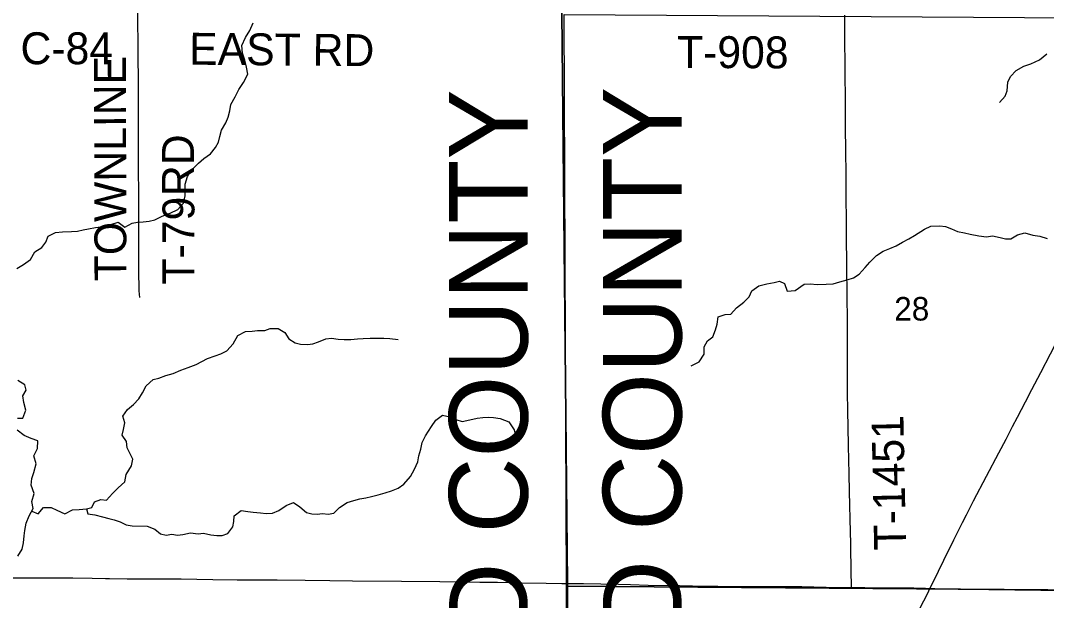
# Model space of a CAD drawing. Extents: x 0 to 70.2, y 0 to 31.4.
# Drawn here: x 5.776 to 7.601, y 19.29 to 20.322 of the extents above; entities that cross this region are included whole.
import ezdxf

# ---------------------------------------------------------------- set-up
doc = ezdxf.new("R2010")
doc.units = 0
for name, color, linetype in [('GM_X_County_Road', 7, 'Continuous'), ('GM_X_County_Road_Text', 7, 'Continuous'), ('GM_X_Minor_River', 7, 'Continuous'), ('GM_X_Section', 7, 'Continuous'), ('GM_X_Section_Text', 7, 'Continuous'), ('GM_X_State_Route', 7, 'Continuous'), ('GM_X_Township_Road', 7, 'Continuous'), ('GM_X_Township_Road_Text', 7, 'Continuous'), ('SH_Cut_Line', 7, 'Continuous'), ('SH_Text', 7, 'Continuous')]:
    doc.layers.add(name, color=color, linetype=linetype)

msp = doc.modelspace()

# ---------------------------------------------------------------- linework, layer by layer
at = {"layer": 'GM_X_County_Road'}
msp.add_lwpolyline([(7.3941, 19.311), (7.403, 19.311), (7.4442, 19.31), (7.4991, 19.3095), (7.5914, 19.3084), (7.6909, 19.3076), (7.7157, 19.3075), (7.7468, 19.3072), (7.7779, 19.3068), (7.8121, 19.3068), (7.868, 19.3063), (7.8928, 19.3063), (7.9239, 19.3068), (7.9394, 19.3066), (7.9518, 19.3064), (8.014, 19.3062), (8.0793, 19.3059), (8.1383, 19.3056), (8.1632, 19.3054), (8.1911, 19.3053), (8.2253, 19.3053), (8.2408, 19.3052), (8.2663, 19.3051), (8.2677, 19.3051)], dxfattribs=at)
at = {"layer": 'GM_X_Minor_River'}
for points in [[(6.0558, 19.9858), (6.0661, 19.9971), (6.0692, 20.01), (6.0689, 20.0202), (6.0689, 20.0312), (6.0732, 20.0445), (6.0797, 20.0551), (6.0926, 20.0683), (6.1022, 20.0766), (6.114, 20.0849), (6.1231, 20.0959), (6.1285, 20.1057), (6.1308, 20.1156), (6.1335, 20.1269), (6.1412, 20.1402), (6.1454, 20.15), (6.1485, 20.1614), (6.1501, 20.1728), (6.1581, 20.1864), (6.1646, 20.1997), (6.173, 20.2121), (6.1807, 20.2265), (6.1785, 20.2391), (6.1751, 20.2516), (6.1714, 20.2641), (6.1699, 20.2778), (6.1764, 20.2918), (6.1841, 20.3047), (6.1899, 20.3179)], [(7.5177, 20.1763), (7.5276, 20.1873), (7.5314, 20.1971), (7.5329, 20.2127), (7.5371, 20.2225), (7.5473, 20.2335), (7.561, 20.2407), (7.5735, 20.2453), (7.5887, 20.2525), (7.602, 20.2631)], [(5.7696, 19.8809), (5.7814, 19.8877), (5.794, 19.8971), (5.8016, 19.9103), (5.8142, 19.9179), (5.821, 19.9277), (5.8257, 19.9383), (5.8382, 19.9447), (5.8511, 19.9458), (5.8667, 19.9464), (5.8777, 19.9475), (5.8879, 19.9494), (5.8974, 19.9516), (5.9096, 19.9538), (5.9236, 19.9557), (5.9369, 19.9594), (5.9499, 19.9635), (5.9619, 19.9543), (5.9749, 19.9615), (5.9844, 19.963), (5.9946, 19.964), (6.0053, 19.9651), (6.0151, 19.9674), (6.0284, 19.9737), (6.0425, 19.9794), (6.0558, 19.9858)], [(6.9695, 19.7073), (6.9835, 19.7149), (6.9926, 19.7281), (6.9926, 19.7414), (6.9983, 19.752), (7.0078, 19.7592), (7.0123, 19.7714), (7.0154, 19.7816), (7.0173, 19.7945), (7.0298, 19.7991), (7.0397, 19.7998), (7.0499, 19.8108), (7.0628, 19.821), (7.0723, 19.8301), (7.0772, 19.8411), (7.0897, 19.8502), (7.1038, 19.8533), (7.1167, 19.8559), (7.1262, 19.8582), (7.1356, 19.8544), (7.1402, 19.8404), (7.1542, 19.8419), (7.1705, 19.8529), (7.1808, 19.8536), (7.1933, 19.8525), (7.2092, 19.8528), (7.2217, 19.8536), (7.2335, 19.857), (7.2468, 19.8608), (7.2578, 19.8642), (7.268, 19.8706), (7.2786, 19.8824), (7.287, 19.8919), (7.2987, 19.904), (7.3109, 19.9116), (7.3226, 19.9165), (7.334, 19.9214), (7.3454, 19.9275), (7.3564, 19.9339), (7.3667, 19.9396), (7.3841, 19.951), (7.3955, 19.9559), (7.4114, 19.957), (7.4217, 19.9555), (7.4323, 19.9513), (7.4433, 19.9468), (7.4558, 19.9441), (7.4656, 19.9422), (7.4808, 19.9388), (7.4948, 19.9373), (7.5051, 19.9392), (7.5187, 19.9361), (7.5282, 19.9335), (7.5377, 19.9338), (7.5498, 19.941), (7.5627, 19.9444), (7.5768, 19.9399), (7.5893, 19.9384), (7.6025, 19.9342)], [(5.7962, 19.449), (5.8077, 19.4442), (5.8173, 19.4555), (5.8305, 19.4555), (5.8408, 19.4505), (5.8548, 19.4444), (5.8685, 19.4515), (5.8806, 19.4518), (5.8935, 19.4533), (5.903, 19.4555), (5.908, 19.4657), (5.919, 19.4699), (5.9289, 19.4687), (5.9396, 19.4804), (5.9502, 19.4902), (5.9617, 19.5008), (5.964, 19.5144), (5.9736, 19.5296), (5.9759, 19.5413), (5.9714, 19.5512), (5.9661, 19.5619), (5.9647, 19.5729), (5.9571, 19.5843), (5.9595, 19.5945), (5.9618, 19.6063), (5.9584, 19.6177), (5.9668, 19.6298), (5.9775, 19.6385), (5.987, 19.6491), (5.9935, 19.6596), (5.9997, 19.6721), (6.0123, 19.6835), (6.0221, 19.6857), (6.035, 19.6902), (6.048, 19.6939), (6.0617, 19.6996), (6.0746, 19.7044), (6.0886, 19.71), (6.0985, 19.7153), (6.1088, 19.7206), (6.1225, 19.7254), (6.1328, 19.7288), (6.143, 19.7345), (6.1548, 19.7465), (6.1629, 19.7613), (6.1766, 19.7688), (6.1883, 19.7691), (6.1978, 19.7702), (6.2111, 19.7706), (6.2206, 19.7743), (6.2347, 19.7742), (6.2464, 19.7666), (6.2535, 19.7559), (6.2649, 19.7487), (6.2744, 19.746), (6.2865, 19.7455), (6.296, 19.747), (6.3066, 19.75), (6.3196, 19.7556), (6.3294, 19.7571), (6.3416, 19.7551), (6.3518, 19.7543), (6.3636, 19.7543), (6.3757, 19.7557), (6.3856, 19.7564), (6.3985, 19.7567), (6.411, 19.7571), (6.4224, 19.7566), (6.4334, 19.7562), (6.4478, 19.7546)], [(5.771, 19.6144), (5.7805, 19.6144), (5.7858, 19.6288), (5.7821, 19.6425), (5.7803, 19.6542), (5.786, 19.6641), (5.7842, 19.674), (5.7713, 19.6816)], [(5.8934, 19.4533), (5.8957, 19.4442), (5.9086, 19.4426), (5.9223, 19.4387), (5.9333, 19.4356), (5.9427, 19.4333), (5.9534, 19.4298), (5.9643, 19.4248), (5.9746, 19.4225), (6.0015, 19.4224), (6.0151, 19.4166), (6.025, 19.4086), (6.0356, 19.4063), (6.0455, 19.4081), (6.0557, 19.4062), (6.0652, 19.4073), (6.0785, 19.4102), (6.0921, 19.4087), (6.102, 19.4097), (6.1149, 19.4067), (6.1255, 19.4055), (6.135, 19.4058), (6.1449, 19.4092), (6.154, 19.4209), (6.1556, 19.4307), (6.1564, 19.4406), (6.1686, 19.45), (6.1804, 19.4481), (6.1902, 19.4469), (6.2031, 19.4457), (6.2133, 19.4449), (6.2247, 19.4456), (6.2358, 19.4501), (6.2491, 19.4591), (6.2616, 19.4644), (6.273, 19.4564), (6.2847, 19.4464), (6.2942, 19.4441), (6.304, 19.4437), (6.3135, 19.4448), (6.3234, 19.4436), (6.3336, 19.4454), (6.3435, 19.4553), (6.3573, 19.4643), (6.369, 19.468), (6.38, 19.471), (6.3907, 19.4729), (6.4006, 19.4751), (6.4127, 19.4781), (6.4249, 19.4818), (6.4363, 19.4848), (6.4481, 19.4901), (6.4583, 19.4972), (6.4698, 19.5104), (6.4774, 19.5237), (6.4828, 19.5366), (6.4851, 19.5472), (6.4882, 19.5593), (6.4909, 19.5711), (6.4967, 19.5832), (6.5074, 19.5995), (6.515, 19.6108), (6.5272, 19.6195), (6.5401, 19.6168), (6.5507, 19.6118), (6.5617, 19.6087), (6.5758, 19.6113), (6.5883, 19.6142), (6.5985, 19.6157), (6.608, 19.6161), (6.6175, 19.6156), (6.6297, 19.614), (6.6448, 19.6079), (6.6546, 19.5938), (6.6568, 19.5828)], [(5.7717, 19.3689), (5.7793, 19.3813), (5.7817, 19.3923), (5.7829, 19.4052), (5.784, 19.4147), (5.7864, 19.4276), (5.7914, 19.4405), (5.7987, 19.4534), (5.7961, 19.4663), (5.8007, 19.4803), (5.7954, 19.4951), (5.7963, 19.5073), (5.7997, 19.5175), (5.804, 19.533), (5.8002, 19.5471), (5.8064, 19.5607), (5.8068, 19.574), (5.7951, 19.5783), (5.783, 19.5836), (5.7705, 19.5928)]]:
    msp.add_lwpolyline(points, dxfattribs=at)
at = {"layer": 'GM_X_Section'}
for points in [[(7.7445, 20.3265), (7.76, 19.3074), (6.7477, 19.3154), (6.7432, 20.333)], [(6.7477, 19.3154), (7.76, 19.3074), (7.7683, 18.3114), (6.7772, 18.3092), (6.7496, 18.3103)]]:
    msp.add_lwpolyline(points, close=True, dxfattribs=at)
at = {"layer": 'GM_X_Section_Text'}
for points in [[(5.7517, 18.3204), (6.7461, 18.306), (6.749, 19.3206), (6.7395, 20.3365), (6.7343, 20.9), (2.6577, 20.9)], [(8.9, 20.9), (6.7343, 20.9), (6.7395, 20.3365), (6.749, 19.3206), (6.7461, 18.306), (6.7742, 18.3058), (6.8676, 18.3057), (7.2705, 18.3155), (7.2966, 18.3153), (7.3494, 18.3155), (7.3774, 18.3154), (7.4209, 18.3155), (7.4458, 18.3156), (7.4645, 18.3154), (7.5173, 18.3158), (7.5515, 18.3159), (7.5981, 18.3162), (7.6197, 18.3167)]]:
    msp.add_lwpolyline(points, dxfattribs=at)
at = {"layer": 'GM_X_State_Route'}
msp.add_lwpolyline([(7.3763, 19.2754), (7.3903, 19.3031), (7.3941, 19.311), (7.3998, 19.3227), (7.4189, 19.3618), (7.4367, 19.3981), (7.4519, 19.4287), (7.4588, 19.4426), (7.4717, 19.4674), (7.4949, 19.5113), (7.5167, 19.5525), (7.5297, 19.5773), (7.5412, 19.5994), (7.5497, 19.6159), (7.564, 19.6435), (7.5754, 19.6655), (7.5912, 19.6958), (7.6259, 19.7619)], dxfattribs=at)
at = {"layer": 'GM_X_Township_Road'}
for points in [[(5.9882, 19.8293), (5.9876, 19.8411), (5.9873, 19.85), (5.9869, 19.8697), (5.9866, 19.9007), (5.9867, 19.9685), (5.9866, 19.9969), (5.9863, 20.0742), (5.9864, 20.1236), (5.986, 20.1684), (5.986, 20.1914), (5.986, 20.2245), (5.9856, 20.2498), (5.9854, 20.2709), (5.9854, 20.291), (5.9852, 20.3108), (5.9852, 20.3347), (5.9848, 20.3424)], [(7.2545, 19.3131), (7.2543, 19.3195), (7.2538, 19.3382), (7.2532, 19.391), (7.2524, 19.4345), (7.2518, 19.4593), (7.2511, 19.4841), (7.2505, 19.5152), (7.2492, 19.5649), (7.2484, 19.5991), (7.2479, 19.627), (7.2475, 19.6612), (7.2474, 19.6922), (7.2473, 19.7357), (7.2473, 19.7792), (7.2466, 19.8413), (7.2462, 19.8753), (7.2461, 19.8971), (7.2459, 19.9281), (7.2455, 19.9716), (7.2453, 20.0027), (7.2449, 20.0493), (7.2447, 20.0897), (7.2441, 20.1332), (7.2437, 20.1891), (7.2435, 20.2202), (7.2427, 20.3103), (7.2425, 20.332)], [(5.5433, 19.3312), (5.6157, 19.3306), (5.6249, 19.3305), (5.6434, 19.3305), (5.6496, 19.3304), (5.6713, 19.3303), (5.6806, 19.3302), (5.6992, 19.3301), (5.7085, 19.3301), (5.7302, 19.3305), (5.8416, 19.3301), (5.8695, 19.33), (5.9037, 19.3295), (5.9277, 19.3291)], [(5.9277, 19.3291), (5.9347, 19.329), (5.9658, 19.3286), (6, 19.3286), (6.0372, 19.3283), (6.0621, 19.3282), (6.0901, 19.3278), (6.1181, 19.3273), (6.1616, 19.3269), (6.2051, 19.3267), (6.233, 19.3264), (6.2828, 19.3258), (6.3263, 19.3252), (6.3667, 19.3246), (6.4537, 19.324), (6.522, 19.3234), (6.5593, 19.3232), (6.5935, 19.3228), (6.6246, 19.3223), (6.6681, 19.3215), (6.7116, 19.3205), (6.7395, 19.3201), (6.7492, 19.3201)], [(6.7492, 19.3201), (6.7776, 19.3199), (6.8087, 19.3195), (6.8398, 19.3191), (6.8616, 19.3186), (6.8927, 19.3174), (6.9486, 19.3164), (6.9953, 19.3156), (7.017, 19.3151), (7.0511, 19.315), (7.076, 19.3146), (7.1071, 19.3147), (7.1258, 19.3146), (7.1662, 19.3145), (7.2097, 19.3137), (7.2408, 19.3132), (7.2545, 19.3131)], [(7.2545, 19.3131), (7.2781, 19.3129), (7.2998, 19.3125), (7.3371, 19.3124), (7.3652, 19.3124), (7.3861, 19.3116), (7.3941, 19.311)]]:
    msp.add_lwpolyline(points, dxfattribs=at)
at = {"layer": 'SH_Cut_Line'}
for points in [[(6.7786, 18.1369), (6.7742, 18.3058), (6.7461, 18.306), (6.749, 19.3206), (6.7395, 20.3365), (6.7343, 20.9), (2.1, 20.9), (2.1, 14.1)], [(8.9, 14.1), (8.9, 20.9), (6.7343, 20.9), (6.7395, 20.3365), (6.749, 19.3206), (6.7461, 18.306), (6.7742, 18.3058), (6.7786, 18.1369)]]:
    msp.add_lwpolyline(points, dxfattribs=at)

# ---------------------------------------------------------------- texts
at = {"layer": 'GM_X_County_Road_Text'}
for s, rotation, p in [('C-84', 0, (5.7762, 20.2444)), ('EAST RD', 359.5093, (6.0761, 20.2436))]:
    msp.add_text(s, height=0.05682, rotation=rotation, dxfattribs=at).set_placement(p)
at = {"layer": 'GM_X_Section_Text'}
msp.add_text('28', height=0.04186, rotation=0, dxfattribs=at).set_placement((7.3306, 19.7882))
at = {"layer": 'GM_X_Township_Road_Text'}
for s, rotation, p in [('T-908', 359.7207, (6.944, 20.2379)), ('TOWNLINE', 90.1302, (5.9647, 19.8582)), ('RD', 90, (6.0847, 20.0098)), ('T-79', 90, (6.0856, 19.8523)), ('T-1451', 91.1642, (7.3517, 19.3795))]:
    msp.add_text(s, height=0.05682, rotation=rotation, dxfattribs=at).set_placement(p)
at = {"layer": 'SH_Text'}
for s, p in [('RICHLAND COUNTY', (6.6785, 18.4002)), ('ASHLAND COUNTY', (6.9522, 18.4775))]:
    msp.add_text(s, height=0.14, rotation=90, dxfattribs=at).set_placement(p)

doc.saveas('drawing.dxf')
